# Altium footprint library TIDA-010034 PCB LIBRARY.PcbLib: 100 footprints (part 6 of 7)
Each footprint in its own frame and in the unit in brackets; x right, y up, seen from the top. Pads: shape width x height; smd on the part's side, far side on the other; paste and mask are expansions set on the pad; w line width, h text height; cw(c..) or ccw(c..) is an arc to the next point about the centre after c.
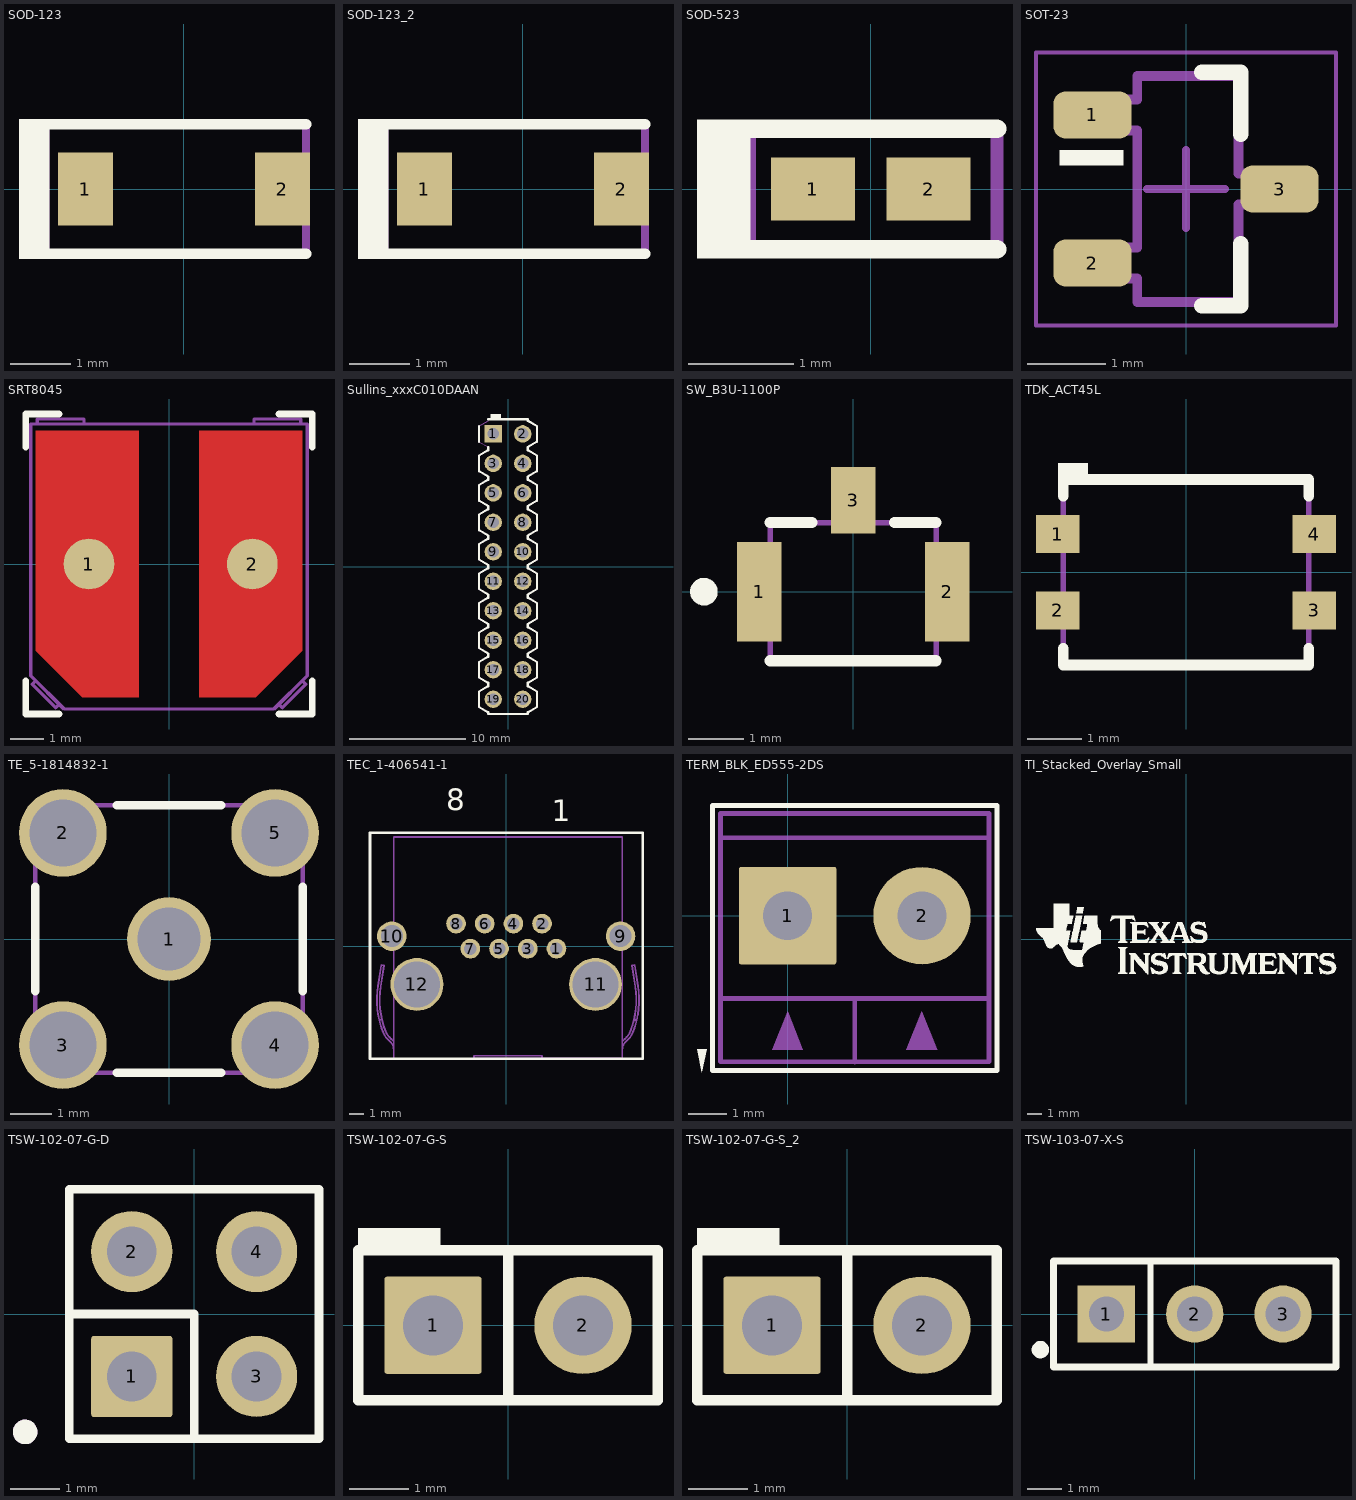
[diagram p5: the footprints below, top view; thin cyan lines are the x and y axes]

## SOD-123 [mm] "On Semi recommended land pattern"
height 1.35
pads (2):
  rect 0.915x1.22 smd: 1(-1.637,0) 2(1.637,0)
Top Overlay:
  rectangle: -2.743,-1.168 -2.235,1.168
  lines w0.178: -2.413,-1.079 2.032,-1.079 ; -2.413,1.079 2.032,1.079
Mechanical 5:
  rectangle: -2.743,-1.168 -2.235,1.168
  lines w0.127: -2.413,-1.079 2.032,-1.079 2.032,1.079 -2.413,1.079
  text ".Designator" at -1.956,-0.33 h0.76
3D body "SOD-123.stp": height 1.35, standoff 0, extent -1.932,-0.9 1.932,0.9

## SOD-123_2 [mm]
pads (2):
  rect 0.915x1.22 smd: 1(-1.637,0) 2(1.637,0)
Top Overlay:
  rectangle: -2.743,-1.168 -2.235,1.168
  lines w0.178: -2.413,-1.079 2.032,-1.079 ; -2.413,1.079 2.032,1.079
Mechanical 5:
  rectangle: -2.743,-1.168 -2.235,1.168
  lines w0.127: -2.413,-1.079 2.032,-1.079 2.032,1.079 -2.413,1.079
  text ".Designator" at -1.956,-0.33 h0.76
3D body "SOD-123.stp": height 1.35, standoff 0, extent -1.932,-0.9 1.932,0.9

## SOD-523 [mm] "NXP Semiconductor recommended land pattern, nominal STEP model"
height 0.7
pads (2):
  rect 0.8x0.6 smd paste-0.05: 1(-0.55,0) 2(0.55,0)
Top Overlay:
  rectangle: -1.651,-0.66 -1.143,0.66
  lines w0.178: -1.475,-0.572 0,-0.572 1.2,-0.572 ; -1.475,0.572 0,0.572 1.2,0.572
Mechanical 5:
  rectangle: -1.6,-0.635 -1.092,0.635
  lines w0.127: -1.475,-0.546 0,-0.546 1.2,-0.546 1.2,0.546 0,0.559 -1.475,0.559
  text ".Designator" at -0.991,-0.279 h0.56
3D body "SOD-523F.stp": height 0.72, standoff 0.02, extent -0.8,-0.399 0.8,0.399

## SOT-23 [mm] "SOT23, 3-Leads, Body 2.9x1.3mm, Pitch 0.95mm, Lead Span 2.5mm, IPC Medium Density"
height 1.1
pads (3):
  rrect50% 1x0.6 smd: 1(-1.2,0.95) 2(-1.2,-0.95) 3(1.2,0)
Top Overlay:
  rectangle: -1.625,0.3 -0.8,0.5
  lines w0.2: 0.2,-1.5 0.7,-1.5 0.7,-0.7 ; 0.2,1.5 0.7,1.5 0.7,0.7
Mechanical 5:
  lines w0.127: -1.16,-1.15 -1.16,-0.75 -0.625,-0.75 -0.625,0.75 -1.16,0.75 -1.16,1.15 -0.625,1.15 -0.625,1.45 0.675,1.45 0.675,0.2 1.21,0.2 1.21,-0.2 0.675,-0.2 0.675,-1.45 -0.625,-1.45 -0.625,-1.15 -1.16,-1.15
  text ".Designator" at -0.175,1.225 h0.64
Mechanical 15:
  lines w0.05: -1.925,-1.75 1.925,-1.75 1.925,1.75 -1.925,1.75 -1.925,-1.75
  lines w0.1: -0.5,0 0.5,0 ; 0,-0.5 0,0.5
3D body "SW3dPS-sot-3p290x130ll237h100.STEP": height 1, standoff 0, extent -1.16,-1.45 1.21,1.45

## SRT8045 [mil] "SMD, 2-Leads, Body 8x8.4mm"
height 181.1
pads (2):
  round 60 smd: 1(-94.49,0) 2(98.43,0)
Top Layer:
  region: -157.48,-102.36 -102.36,-157.48 -35.43,-157.48 -35.43,157.48 -157.48,157.48
  region: 157.48,-102.36 102.36,-157.48 35.43,-157.48 35.43,157.48 157.48,157.48
Top Overlay:
  lines w7.87: -169.29,-137.8 -169.29,-177.17 -129.92,-177.17 ; -169.29,137.8 -169.29,177.17 -129.92,177.17 ; 129.92,-177.17 169.29,-177.17 169.29,-137.8 ; 129.92,177.17 169.29,177.17 169.29,137.8
Mechanical 5:
  lines w3.94: -157.62,-137.66 -161.8,-141.83 -133.96,-169.67 -129.78,-165.49 ; -155.51,165.35 -155.51,171.26 -100.39,171.26 -100.39,165.35 ; 100.39,165.35 100.39,171.26 155.51,171.26 155.51,165.35 ; 129.78,-165.49 133.96,-169.67 161.8,-141.83 157.62,-137.66 ; -163.39,-131.89 -124.02,-171.26 124.02,-171.26 163.39,-131.89 163.39,165.35 -163.39,165.35 -163.39,-131.89
  text ".Designator" at -205.56,-32.66 h40
3D body "Coilcraft-SRT8045.stp": height 181.1, standoff 0, extent -163.39,-171.45 163.38,171.07

## Sullins_xxxC010DAAN [mm] "Header, 2.54mm, 10x2, TH"
height 8.74
pads (20):
  rect 1.5x1.5 hole 1: 1(-1.27,11.43)
  round 1.5 hole 1: 2(1.27,11.43) 3(-1.27,8.89) 4(1.27,8.89) 5(-1.27,6.35) 6(1.27,6.35) 7(-1.27,3.81) 8(1.27,3.81) 9(-1.27,1.27) 10(1.27,1.27) 11(-1.27,-1.27) 12(1.27,-1.27) 13(-1.27,-3.81) 14(1.27,-3.81) 15(-1.27,-6.35) 16(1.27,-6.35) 17(-1.27,-8.89) 18(1.27,-8.89) 19(-1.27,-11.43) 20(1.27,-11.43)
Top Overlay:
  rectangle: -1.5,12.7 -0.6,13.14
  lines w0.2: -2.5,10.76 -2.5,12.1 ; -1.7,-7.62 -1.7,-7.482 ; -1.7,10.298 -1.7,10.022 -2.5,9.56 -2.5,8.22 -1.7,7.758 -1.7,7.482 -2.5,7.02 -2.5,5.68 -1.7,5.218 -1.7,4.942 -2.5,4.48 -2.5,3.14 -1.7,2.678 -1.7,2.402 -2.5,1.94 -2.5,0.6 -1.7,0.138 -1.7,-0.138 -2.5,-0.6 -2.5,-1.94 -1.7,-2.402 -1.7,-2.678 -2.5,-3.14 -2.5,-4.48 -1.7,-4.942 -1.7,-5.218 -2.5,-5.68 -2.5,-7.02 -1.7,-7.482 ; -1.7,12.7 1.7,12.7 1.7,12.562 2.5,12.1 2.5,10.76 1.7,10.298 1.7,10.022 2.5,9.56 2.5,8.22 1.7,7.758 1.7,7.482 2.5,7.02 2.5,5.68 1.7,5.218 1.7,4.942 2.5,4.48 2.5,3.14 1.7,2.678 1.7,2.402 2.5,1.94 2.5,0.6 1.7,0.138 1.7,-0.138 2.5,-0.6 2.5,-1.94 1.7,-2.402 1.7,-2.678 2.5,-3.14 2.5,-4.48 1.7,-4.942 1.7,-5.218 2.5,-5.68 2.5,-7.02 1.7,-7.482 ; 1.7,-7.62 1.7,-7.482 ; -1.7,-7.482 -1.7,-7.758 -2.5,-8.22 -2.5,-9.56 -1.7,-10.022 -1.7,-10.298 -2.5,-10.76 -2.5,-12.1 -1.7,-12.562 -1.7,-12.7 1.7,-12.7 1.7,-12.562 2.5,-12.1 2.5,-10.76 1.7,-10.298 1.7,-10.022 2.5,-9.56 2.5,-8.22 1.7,-7.758 1.7,-7.482
Mechanical 5:
  lines w0.1: -2.5,-12.1 -1.7,-12.562 -1.7,-12.7 1.7,-12.7 1.7,-12.562 2.5,-12.1 2.5,-10.76 1.7,-10.298 1.7,-10.022 2.5,-9.56 2.5,-8.22 1.7,-7.758 1.7,-7.482 2.5,-7.02 2.5,-5.68 1.7,-5.218 1.7,-4.942 2.5,-4.48 2.5,-3.14 1.7,-2.678 1.7,-2.402 2.5,-1.94 2.5,-0.6 1.7,-0.138 1.7,0.138 2.5,0.6 2.5,1.94 1.7,2.402 1.7,2.678 2.5,3.14 2.5,4.48 1.7,4.942 1.7,5.218 2.5,5.68 2.5,7.02 1.7,7.482 1.7,7.758 2.5,8.22 2.5,9.56 1.7,10.022 1.7,10.298 2.5,10.76 2.5,12.1 1.7,12.562 1.7,12.7 -1.7,12.7 -1.7,12.562 -2.5,12.1 -2.5,10.76 -1.7,10.298 -1.7,10.022 -2.5,9.56 -2.5,8.22 -1.7,7.758 -1.7,7.482 -2.5,7.02 -2.5,5.68 -1.7,5.218 -1.7,4.942 -2.5,4.48 -2.5,3.14 -1.7,2.678 -1.7,2.402 -2.5,1.94 -2.5,0.6 -1.7,0.138 -1.7,-0.138 -2.5,-0.6 -2.5,-1.94 -1.7,-2.402 -1.7,-2.678 -2.5,-3.14 -2.5,-4.48 -1.7,-4.942 -1.7,-5.218 -2.5,-5.68 -2.5,-7.02 -1.7,-7.482 -1.7,-7.758 -2.5,-8.22 -2.5,-9.56 -1.7,-10.022 -1.7,-10.298 -2.5,-10.76 -2.5,-12.1
  text ".Designator" at -2.2,-1.8 h1.02
3D body "PRPC010DAAN-RC.stp": height 8.34, standoff -3.05, extent -2.5,-12.7 2.5,12.7

## SW_B3U-1100P [mm] "SMD, 3-Leads, Body 3x2.5mm"
height 1.75
pads (3):
  rect 0.8x1.8 smd: 1(-1.7,0) 2(1.7,0)
  rect 0.8x1.2 smd: 3(0,1.65)
Top Overlay:
  circle w0.25: c-2.7,0 r0.125
  lines w0.2: -1.5,-1.25 1.5,-1.25 ; -1.5,1.25 -0.75,1.25 ; 0.75,1.25 1.5,1.25
Mechanical 5:
  lines w0.1: -1.5,-0.7 -2,-0.7 -2,0.7 -1.5,0.7 ; -0.25,1.25 -0.25,1.9 0.25,1.9 0.25,1.25 ; -0.25,1.55 0.25,1.55 ; 1.5,-0.7 2,-0.7 2,0.7 1.5,0.7 ; -1.5,-1.25 1.5,-1.25 1.5,1.25 -1.5,1.25 -1.5,-1.25
  text ".Designator" at -0.7,-0.225 h0.5
3D body: height 1.6, standoff 0, extent -2,-1.25 2,1.9

## TDK_ACT45L [mm] "SMD, 4-Leads, Body 4.5x3.2mm"
height 2.95
pads (4):
  rect 0.8x0.7 smd: 1(-2.35,0.7) 2(-2.35,-0.7) 3(2.35,-0.7) 4(2.35,0.7)
Top Overlay:
  rectangle: -2.35,1.7 -1.8,2
  lines w0.2: -2.25,-1.4 -2.25,-1.7 2.25,-1.7 2.25,-1.4 ; -2.25,1.4 -2.25,1.7 2.25,1.7 2.25,1.4
Mechanical 5:
  lines w0.1: -2.25,-1.7 -2.25,1.7 2.25,1.7 2.25,-1.7 -2.25,-1.7
  text ".Designator" at -1.8,-0.7 h1.85
3D body "ACT45L.stp": height 2.95, standoff 0, extent -2.252,-1.7 2.252,1.7

## TE_5-1814832-1 [mm] "SMA Straight PCB Socket Die Cast, TH"
height 9.5
pads (5):
  round 2 hole 1.5: 1(0,0)
  round 2.1 hole 1.6: 2(-2.54,2.54) 3(-2.54,-2.54) 4(2.54,-2.54) 5(2.54,2.54)
Top Overlay:
  lines w0.2: -3.2,-1.249 -3.2,1.249 ; -1.249,-3.2 1.249,-3.2 ; -1.249,3.2 1.249,3.2 ; 3.2,-1.249 3.2,1.249
Mechanical 5:
  lines w0.1: -3.2,-3.2 3.2,-3.2 3.2,3.2 -3.2,3.2 -3.2,-3.2
  text ".Designator" at -1.524,-0.508 h1.02
3D body "c-5-1814832-1-b-3d.stp": height 9.5, standoff -4, extent -3.2,-3.2 3.2,3.2

## TEC_1-406541-1 [mm] "TE Connectivity"
height 15.04
pads (12):
  round 1.4 hole 0.89: 1(3.56,-0.18) 2(2.54,1.6) 3(1.52,-0.18) 4(0.5,1.6) 5(-0.52,-0.18) 6(-1.54,1.6) 7(-2.56,-0.18) 8(-3.58,1.6)
  round 2.1 hole 1.57: 9(8.12,0.71) 10(-8.14,0.71)
  round 3.759 hole 3.251: 11(6.34,-2.72) 12(-6.36,-2.72)
Top Overlay:
  lines w0.2: -9.695,8.03 -9.695,-8 9.695,-8 9.695,8.06 -9.695,8.06
  text "8" at -4.272,9.652 h1.52
  text "1" at 3.221,8.89 h1.52
Mechanical 5:
  lines w0.127: -8.011,-8 -2.296,-8 ; -8.011,-7.989 -8.011,7.759 8.245,7.759 8.245,-7.989 2.53,-7.989 ; -8.011,-7.354 ccw(c-8.773,-7.354) -8.296,-6.759 cw(c-7.327,-5.549) -8.772,-6.112 cw(c-2.855,-3.807) -9.044,-5.225 ; -8.011,-6.773 ccw(c-8.773,-7.354) -8.174,-6.606 cw(c-7.327,-5.549) -8.589,-6.041 cw(c-2.855,-3.807) -8.844,-5.225 ; 8.245,-7.354 cw(c9.007,-7.354) 8.53,-6.759 ccw(c7.561,-5.549) 9.006,-6.112 ccw(c3.089,-3.807) 9.273,-5.251 ; 8.245,-6.774 cw(c9.007,-7.354) 8.408,-6.607 ccw(c7.561,-5.549) 8.823,-6.041 ccw(c3.089,-3.807) 9.071,-5.251 ; -9.044,-5.225 cw(c-2.855,-3.807) -9.132,-2.845 -8.9,-1.334 -8.707,-1.364 -8.938,-2.875 ccw(c-2.855,-3.807) -8.844,-5.225 ; -9.044,-5.225 -8.844,-5.225 ; 2.53,-7.989 2.53,-7.793 -2.296,-7.793 -2.296,-7.989 2.53,-7.989 ; 9.071,-5.251 ccw(c3.089,-3.807) 9.172,-2.875 8.941,-1.364 9.134,-1.334 9.366,-2.845 cw(c3.089,-3.807) 9.273,-5.251 ; 9.071,-5.251 9.273,-5.251
  text ".Designator" at -1.885,-0.5 h1.02
3D body "TEC_1-406541-1.stp": height 14.8, standoff -3.92, extent -9.33,-7.998 9.31,7.75

## TERM_BLK_ED555-2DS [mil]
height 322.83
pads (2):
  rrect4% 100x100 hole 50: 1(0,0)
  round 100 hole 50: 2(138,0)
Top Overlay:
  region: -88,-161 -83,-137 -93,-137
  lines w5: -77,-159 215,-159 215,113 -77,113 -77,-159
Mechanical 5:
  region: 153.54,-137.8 122.05,-137.8 137.8,-98.43
  region: 15.75,-137.8 -15.75,-137.8 0,-98.43
  lines w5: -68.9,-85 206.69,-85 ; -68.9,80 206.69,80 ; 68.9,-150.2 68.9,-85 ; -68.9,-150 206.69,-150 206.69,105 -68.9,105 -68.9,-150
  text ".Designator" at -23.62,-23.62 h40
3D body "On-Shore_ED555_2DS.stp": height 323.43, standoff -137.2, extent -68.7,-149.61 206.89,106.29

## TI_Stacked_Overlay_Small [mm]
Top Overlay:
  drawing of 18 lines, arcs and shapes, not listed

## TSW-102-07-G-D [mm] "Samtec 100mil, 2x2, 230 mil above insulator"
height 8.382
pads (4):
  rrect6% 1.65x1.65 hole 1.016: 1(-1.27,-1.27)
  round 1.65 hole 1.016: 2(-1.27,1.27) 3(1.27,-1.27) 4(1.27,1.27)
Top Overlay:
  circle w0.25: c-3.44,-2.4 r0.125
  lines w0.178: -2.54,0 0,0 0,-2.54 ; -2.54,-2.54 -2.54,2.54 2.54,2.54 2.54,-2.54 -2.54,-2.54
Mechanical 5:
  circle w0.25: c-3.44,-2.4 r0.125
  lines w0.127: -2.54,-2.54 2.54,-2.54 2.54,2.54 -2.54,2.54 -2.54,-2.54
  text ".Designator" at -1.524,-0.508 h1.02
3D body "SamtecTSW-07_2x2.stp": height 8.38, standoff -2.54, extent -2.54,-2.54 2.54,2.54

## TSW-102-07-G-S [mm] "Samtec 100mil, 1x2, 230 mil above insulator"
height 8.382
pads (2):
  rrect6% 1.65x1.65 hole 1.016: 1(-1.27,0)
  round 1.65 hole 1.016: 2(1.27,0)
Top Overlay:
  rectangle: -2.54,1.27 -1.143,1.651
  lines w0.178: 0,-1.27 0,1.27 ; -2.54,-1.27 2.54,-1.27 2.54,1.27 -2.54,1.27 -2.54,-1.27
Mechanical 5:
  lines w0.127: -2.54,-1.27 -2.54,1.27 2.54,1.27 2.54,-1.27 -2.54,-1.27
  text ".Designator" at -1.524,-0.508 h1.02
3D body "SamtecTSW-07_2x1.stp": height 8.38, standoff -2.54, extent -2.54,-1.27 2.54,1.27

## TSW-102-07-G-S_2 [mm]
pads (2):
  rrect6% 1.65x1.65 hole 1.016: 1(-1.27,0)
  round 1.65 hole 1.016: 2(1.27,0)
Top Overlay:
  rectangle: -2.54,1.27 -1.143,1.651
  lines w0.178: 0,-1.27 0,1.27 ; -2.54,-1.27 2.54,-1.27 2.54,1.27 -2.54,1.27 -2.54,-1.27
Mechanical 5:
  lines w0.127: -2.54,-1.27 -2.54,1.27 2.54,1.27 2.54,-1.27 -2.54,-1.27
  text ".Designator" at -1.524,-0.508 h1.02
3D body "SamtecTSW-07_2x1.stp": height 8.38, standoff -2.54, extent -2.54,-1.27 2.54,1.27

## TSW-103-07-X-S [mm] "Samtec Header, 100mil, 1x3"
height 8.382
pads (3):
  rect 1.65x1.65 hole 1.016: 1(-2.54,0)
  round 1.65 hole 1.016: 2(0,0) 3(2.54,0)
Top Overlay:
  circle w0.25: c-4.441,-1.025 r0.125
  lines w0.178: -1.27,-1.524 -1.27,1.46
  lines w0.2: -4.064,-1.524 -4.064,1.524 4.064,1.524 4.064,-1.524 -4.064,-1.524
Mechanical 5:
  rectangle: -3.048,-0.508 -2.032,0.508
  lines w0.127: -4.064,-1.524 4.064,-1.524 4.064,1.524 -4.064,1.524 -4.064,-1.524
  text ".Designator" at -1.27,-0.508 h1.02
3D body "SamtecTSW-07_3x1.stp": height 8.38, standoff -2.54, extent -3.81,-1.27 3.81,1.27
